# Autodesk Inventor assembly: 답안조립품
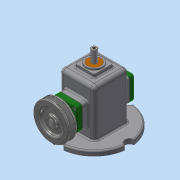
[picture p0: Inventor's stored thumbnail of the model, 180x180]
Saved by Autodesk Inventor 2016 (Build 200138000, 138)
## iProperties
Created: 2018-07
Part Number: 답안조립품
Material: 일반
Document SubType Name: Assembly
Designer: 2-PC06
Author: 2-PC06
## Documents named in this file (16)
- C:\Users\2-PC06\Desktop\480708V1006\답안조립품.iam
- C:\Users\2-PC06\Desktop\480708V1006\본체.ipt
- C:\Users\2-PC06\Desktop\480708V1006\V벨트풀리.ipt
- C:\Users\2-PC06\Desktop\480708V1006\고정핀 1.2x8.ipt
- C:\Users\2-PC06\Desktop\480708V1006\뒤커버.ipt
- C:\Users\2-PC06\Desktop\480708V1006\링크.ipt
- C:\Users\2-PC06\Desktop\480708V1006\멈춤나사 M3x8.ipt
- C:\Users\2-PC06\Desktop\480708V1006\베어링 12x32x10.ipt
- C:\Users\2-PC06\Desktop\480708V1006\볼트 M4.ipt
- C:\Users\2-PC06\Desktop\480708V1006\부시.ipt
- C:\Users\2-PC06\Desktop\480708V1006\슬라이드.ipt
- C:\Users\2-PC06\Desktop\480708V1006\앞커버.ipt
- C:\Users\2-PC06\Desktop\480708V1006\오일 실 12 25 7.ipt
- C:\Users\2-PC06\Desktop\480708V1006\키 4x4x10.ipt
- C:\Users\2-PC06\Desktop\480708V1006\편심축.ipt
- C:\Users\2-PC06\Desktop\480708V1006\핀 5x18.ipt
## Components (3 placed, 3 different names)
1. V벨트풀리:1
2. 고정핀 1.2x8:1
3. 핀 5x18:1
